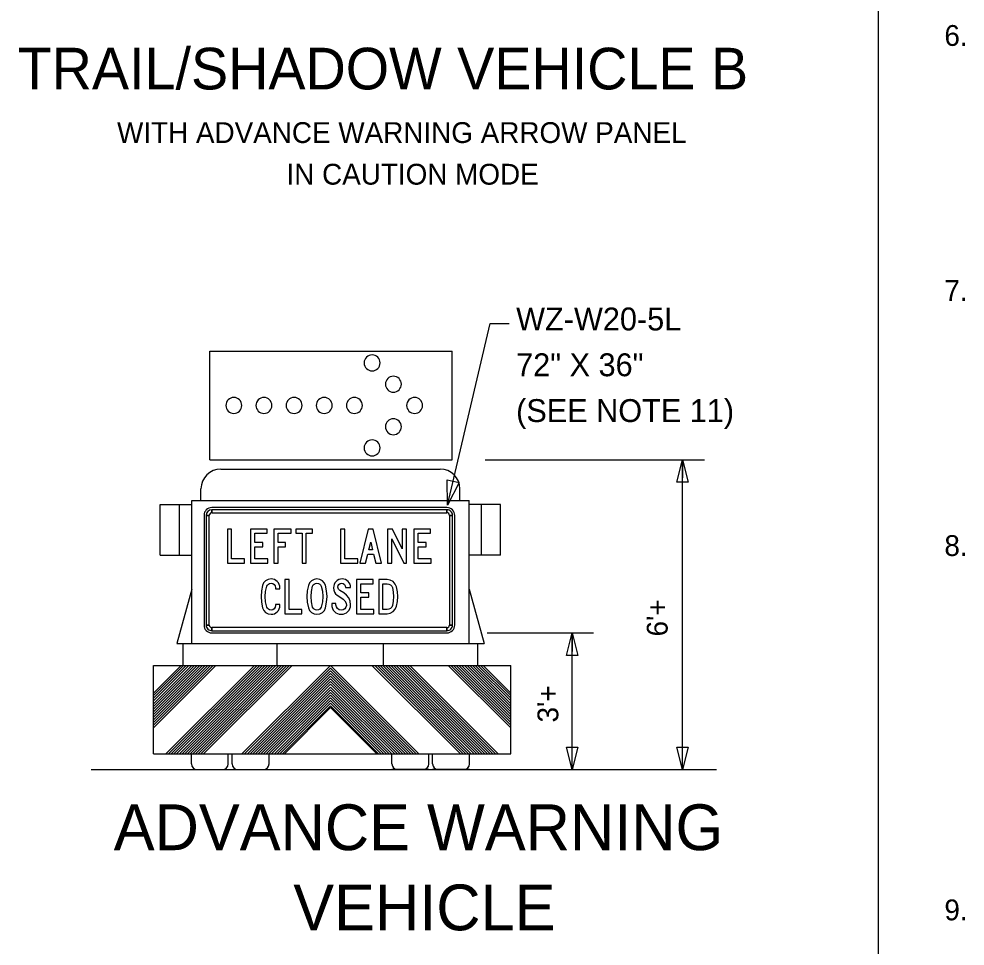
# Model space of a CAD drawing. Extents: x 1373848 to 1374003, y 380642 to 381248.
# Drawn here: x 1373929.73 to 1373956.99, y 381003.36 to 381030.08 of the extents above; entities that cross this region are included whole.
import ezdxf

# ---------------------------------------------------------------- set-up
doc = ezdxf.new("R2010")
doc.units = 0
doc.layers.add('Working Level 1', color=7, linetype='Continuous')

msp = doc.modelspace()

# ---------------------------------------------------------------- linework, layer by layer
at = {"layer": 'Working Level 1'}
for p, q in [((1373954.481, 381081.277), (1373954.481, 380977.045)), ((1373935.233, 381020.5), (1373942.211, 381020.5)), ((1373935.233, 381017.372), (1373935.233, 381020.5)), ((1373942.211, 381017.372), (1373942.211, 381020.5)), ((1373935.233, 381017.372), (1373942.211, 381017.372)), ((1373943.157, 381017.372), (1373949.484, 381017.372)), ((1373948.848, 381008.44), (1373948.848, 381017.372)), ((1373948.848, 381017.372), (1373948.848, 381016.848)), ((1373935.548, 381017.104), (1373941.862, 381017.104)), ((1373934.974, 381016.201), (1373934.974, 381016.53)), ((1373942.436, 381016.201), (1373942.436, 381016.53)), ((1373934.714, 381012.074), (1373934.714, 381016.201)), ((1373934.714, 381016.201), (1373942.696, 381016.201)), ((1373942.696, 381012.074), (1373942.696, 381016.201)), ((1373933.803, 381016.084), (1373934.714, 381016.084)), ((1373933.803, 381014.617), (1373933.803, 381016.084)), ((1373934.354, 381014.617), (1373934.354, 381016.084)), ((1373942.059, 381015.994), (1373935.288, 381015.994)), ((1373935.288, 381015.843), (1373935.288, 381015.931)), ((1373942.059, 381015.931), (1373942.059, 381015.843)), ((1373943.607, 381016.084), (1373942.696, 381016.084)), ((1373943.055, 381014.617), (1373943.055, 381016.084)), ((1373943.607, 381014.617), (1373943.607, 381016.084)), ((1373935.062, 381015.768), (1373935.062, 381012.608)), ((1373935.125, 381015.768), (1373935.213, 381015.768)), ((1373942.135, 381015.768), (1373942.222, 381015.768)), ((1373942.285, 381012.608), (1373942.285, 381015.768)), ((1373933.803, 381014.617), (1373934.714, 381014.617)), ((1373943.607, 381014.617), (1373942.696, 381014.617)), ((1373934.714, 381013.646), (1373934.282, 381012.074)), ((1373942.696, 381013.646), (1373943.128, 381012.074)), ((1373935.213, 381012.608), (1373935.125, 381012.608)), ((1373935.288, 381012.445), (1373935.288, 381012.533)), ((1373935.288, 381012.382), (1373942.059, 381012.382)), ((1373942.059, 381012.533), (1373942.059, 381012.445)), ((1373942.222, 381012.608), (1373942.135, 381012.608)), ((1373943.223, 381012.382), (1373946.284, 381012.382)), ((1373945.667, 381008.44), (1373945.667, 381012.382)), ((1373945.667, 381012.382), (1373945.667, 381011.85)), ((1373934.282, 381012.074), (1373943.128, 381012.074)), ((1373934.461, 381011.444), (1373934.461, 381012.074)), ((1373942.949, 381011.444), (1373942.949, 381012.074)), ((1373937.173, 381011.444), (1373937.173, 381012.063)), ((1373940.237, 381011.444), (1373940.237, 381012.063)), ((1373933.604, 381011.444), (1373943.899, 381011.444)), ((1373933.604, 381011.444), (1373943.899, 381011.444)), ((1373933.604, 381011.444), (1373943.899, 381011.444)), ((1373933.604, 381011.444), (1373943.899, 381011.444)), ((1373933.604, 381008.894), (1373933.604, 381011.444)), ((1373933.604, 381010.646), (1373934.402, 381011.444)), ((1373933.604, 381009.718), (1373935.33, 381011.444)), ((1373933.604, 381009.796), (1373935.252, 381011.444)), ((1373933.604, 381009.874), (1373935.174, 381011.444)), ((1373933.604, 381009.951), (1373935.097, 381011.444)), ((1373933.604, 381010.029), (1373935.019, 381011.444)), ((1373933.604, 381010.107), (1373934.941, 381011.444)), ((1373933.604, 381010.184), (1373934.864, 381011.444)), ((1373933.604, 381010.263), (1373934.786, 381011.444)), ((1373933.604, 381010.341), (1373934.707, 381011.444)), ((1373933.604, 381010.419), (1373934.629, 381011.444)), ((1373933.604, 381010.496), (1373934.552, 381011.444)), ((1373933.604, 381010.574), (1373934.474, 381011.444)), ((1373933.604, 381009.641), (1373935.405, 381011.442)), ((1373933.963, 381008.894), (1373936.513, 381011.444)), ((1373934.041, 381008.894), (1373936.591, 381011.444)), ((1373934.119, 381008.894), (1373936.669, 381011.444)), ((1373934.197, 381008.894), (1373936.747, 381011.444)), ((1373934.274, 381008.894), (1373936.824, 381011.444)), ((1373934.352, 381008.894), (1373936.902, 381011.444)), ((1373934.43, 381008.894), (1373936.98, 381011.444)), ((1373934.508, 381008.894), (1373937.058, 381011.444)), ((1373934.585, 381008.894), (1373937.135, 381011.444)), ((1373934.663, 381008.894), (1373937.213, 381011.444)), ((1373934.742, 381008.894), (1373937.291, 381011.444)), ((1373934.819, 381008.894), (1373937.368, 381011.444)), ((1373934.897, 381008.894), (1373937.446, 381011.444)), ((1373934.975, 381008.894), (1373937.523, 381011.443)), ((1373935.052, 381008.894), (1373937.602, 381011.444)), ((1373936.155, 381008.894), (1373938.705, 381011.444)), ((1373936.233, 381008.894), (1373938.705, 381011.366)), ((1373936.311, 381008.894), (1373938.705, 381011.288)), ((1373941.255, 381008.894), (1373938.705, 381011.444)), ((1373941.173, 381008.899), (1373938.705, 381011.366)), ((1373941.1, 381008.894), (1373938.705, 381011.288)), ((1373942.451, 381008.894), (1373939.901, 381011.444)), ((1373942.528, 381008.894), (1373939.98, 381011.443)), ((1373942.607, 381008.894), (1373940.057, 381011.444)), ((1373942.685, 381008.894), (1373940.135, 381011.444)), ((1373942.762, 381008.894), (1373940.212, 381011.444)), ((1373942.84, 381008.894), (1373940.29, 381011.444)), ((1373942.918, 381008.894), (1373940.368, 381011.444)), ((1373942.995, 381008.894), (1373940.445, 381011.444)), ((1373943.073, 381008.894), (1373940.523, 381011.444)), ((1373943.151, 381008.894), (1373940.601, 381011.444)), ((1373943.229, 381008.894), (1373940.679, 381011.444)), ((1373943.306, 381008.894), (1373940.756, 381011.444)), ((1373943.384, 381008.894), (1373940.834, 381011.444)), ((1373943.462, 381008.894), (1373940.913, 381011.444)), ((1373943.54, 381008.894), (1373940.99, 381011.444)), ((1373943.899, 381009.641), (1373942.098, 381011.442)), ((1373943.899, 381009.718), (1373942.173, 381011.444)), ((1373943.899, 381009.796), (1373942.251, 381011.444)), ((1373943.899, 381009.874), (1373942.329, 381011.444)), ((1373943.899, 381009.951), (1373942.406, 381011.444)), ((1373943.899, 381010.029), (1373942.484, 381011.444)), ((1373943.899, 381010.107), (1373942.563, 381011.444)), ((1373943.899, 381010.184), (1373942.64, 381011.444)), ((1373943.899, 381010.263), (1373942.718, 381011.444)), ((1373943.899, 381010.341), (1373942.796, 381011.444)), ((1373943.899, 381010.419), (1373942.874, 381011.444)), ((1373943.899, 381010.496), (1373942.951, 381011.444)), ((1373943.899, 381010.574), (1373943.029, 381011.444)), ((1373943.899, 381010.646), (1373943.101, 381011.444)), ((1373943.899, 381008.894), (1373943.899, 381011.444)), ((1373936.389, 381008.894), (1373938.705, 381011.21)), ((1373936.466, 381008.894), (1373938.705, 381011.133)), ((1373936.544, 381008.894), (1373938.705, 381011.055)), ((1373941.021, 381008.894), (1373938.705, 381011.21)), ((1373940.944, 381008.894), (1373938.705, 381011.133)), ((1373940.866, 381008.894), (1373938.705, 381011.055)), ((1373936.622, 381008.894), (1373938.705, 381010.977)), ((1373936.699, 381008.894), (1373938.705, 381010.9)), ((1373936.777, 381008.894), (1373938.705, 381010.822)), ((1373936.855, 381008.894), (1373938.705, 381010.744)), ((1373940.788, 381008.894), (1373938.705, 381010.977)), ((1373940.711, 381008.894), (1373938.705, 381010.9)), ((1373940.633, 381008.894), (1373938.705, 381010.822)), ((1373940.555, 381008.894), (1373938.705, 381010.744)), ((1373936.933, 381008.894), (1373938.705, 381010.666)), ((1373937.01, 381008.894), (1373938.705, 381010.589)), ((1373937.088, 381008.894), (1373938.705, 381010.511)), ((1373940.477, 381008.894), (1373938.705, 381010.666)), ((1373940.4, 381008.894), (1373938.705, 381010.589)), ((1373940.322, 381008.894), (1373938.705, 381010.511)), ((1373937.167, 381008.894), (1373938.705, 381010.433)), ((1373937.244, 381008.894), (1373938.705, 381010.356)), ((1373937.321, 381008.894), (1373938.705, 381010.278)), ((1373937.387, 381008.909), (1373938.705, 381010.227)), ((1373940.244, 381008.894), (1373938.705, 381010.433)), ((1373940.167, 381008.894), (1373938.705, 381010.356)), ((1373940.089, 381008.894), (1373938.705, 381010.278)), ((1373940.038, 381008.894), (1373938.705, 381010.227)), ((1373933.604, 381008.894), (1373943.899, 381008.894)), ((1373933.604, 381008.894), (1373943.899, 381008.894)), ((1373933.604, 381008.894), (1373943.899, 381008.894)), ((1373933.604, 381008.894), (1373943.899, 381008.894)), ((1373934.698, 381008.605), (1373934.698, 381008.894)), ((1373935.762, 381008.605), (1373935.762, 381008.894)), ((1373935.872, 381008.605), (1373935.872, 381008.894)), ((1373936.936, 381008.605), (1373936.936, 381008.894)), ((1373940.474, 381008.605), (1373940.474, 381008.894)), ((1373941.538, 381008.605), (1373941.538, 381008.894)), ((1373941.648, 381008.605), (1373941.648, 381008.894)), ((1373942.712, 381008.605), (1373942.712, 381008.894)), ((1373931.816, 381008.44), (1373949.828, 381008.44)), ((1373934.698, 381008.44), (1373935.762, 381008.44)), ((1373934.698, 381008.44), (1373935.762, 381008.44)), ((1373934.698, 381008.44), (1373935.762, 381008.44)), ((1373934.698, 381008.44), (1373935.762, 381008.44)), ((1373935.872, 381008.44), (1373936.936, 381008.44)), ((1373935.872, 381008.44), (1373936.936, 381008.44)), ((1373935.872, 381008.44), (1373936.936, 381008.44)), ((1373935.872, 381008.44), (1373936.936, 381008.44)), ((1373941.538, 381008.44), (1373940.474, 381008.44)), ((1373941.538, 381008.44), (1373940.474, 381008.44)), ((1373941.538, 381008.44), (1373940.474, 381008.44)), ((1373941.538, 381008.44), (1373940.474, 381008.44)), ((1373942.712, 381008.44), (1373941.648, 381008.44)), ((1373942.712, 381008.44), (1373941.648, 381008.44)), ((1373942.712, 381008.44), (1373941.648, 381008.44)), ((1373942.712, 381008.44), (1373941.648, 381008.44))]:
    msp.add_line(p, q, dxfattribs=at)
for points in [[(1373942.074, 381016.059), (1373943.308, 381021.299), (1373943.848, 381021.299)], [(1373940.175, 381014.389), (1373939.935, 381015.374), (1373939.795, 381015.374), (1373939.555, 381014.389), (1373939.718, 381014.389), (1373939.782, 381014.653), (1373939.947, 381014.653), (1373940.012, 381014.389), (1373940.175, 381014.389)], [(1373939.918, 381014.776), (1373939.812, 381014.776), (1373939.865, 381014.993), (1373939.918, 381014.776)], [(1373938.606, 381013.427), (1373938.594, 381013.593), (1373938.561, 381013.753), (1373938.527, 381013.827), (1373938.471, 381013.886), (1373938.398, 381013.924), (1373938.315, 381013.937), (1373938.232, 381013.924), (1373938.159, 381013.885), (1373938.102, 381013.826), (1373938.068, 381013.752), (1373938.036, 381013.592), (1373938.025, 381013.427), (1373938.036, 381013.264), (1373938.068, 381013.104), (1373938.102, 381013.029), (1373938.159, 381012.969), (1373938.232, 381012.93), (1373938.315, 381012.917), (1373938.398, 381012.93), (1373938.472, 381012.969), (1373938.529, 381013.03), (1373938.562, 381013.105), (1373938.595, 381013.265), (1373938.606, 381013.427)], [(1373938.482, 381013.427), (1373938.472, 381013.275), (1373938.439, 381013.126), (1373938.422, 381013.091), (1373938.394, 381013.064), (1373938.357, 381013.046), (1373938.315, 381013.04), (1373938.273, 381013.046), (1373938.237, 381013.064), (1373938.208, 381013.093), (1373938.191, 381013.127), (1373938.159, 381013.276), (1373938.148, 381013.427), (1373938.159, 381013.579), (1373938.191, 381013.727), (1373938.208, 381013.762), (1373938.237, 381013.79), (1373938.273, 381013.808), (1373938.315, 381013.814), (1373938.357, 381013.808), (1373938.394, 381013.79), (1373938.422, 381013.762), (1373938.439, 381013.728), (1373938.472, 381013.58), (1373938.482, 381013.427)], [(1373940.095, 381012.934), (1373940.335, 381012.934), (1373940.428, 381012.949), (1373940.51, 381012.995), (1373940.573, 381013.063), (1373940.609, 381013.148), (1373940.633, 381013.285), (1373940.641, 381013.427), (1373940.633, 381013.568), (1373940.609, 381013.706), (1373940.573, 381013.79), (1373940.51, 381013.859), (1373940.428, 381013.904), (1373940.335, 381013.92), (1373940.095, 381013.92), (1373940.095, 381012.934)], [(1373940.218, 381013.057), (1373940.218, 381013.796), (1373940.339, 381013.796), (1373940.389, 381013.789), (1373940.433, 381013.765), (1373940.468, 381013.729), (1373940.487, 381013.685), (1373940.51, 381013.557), (1373940.517, 381013.427), (1373940.51, 381013.296), (1373940.487, 381013.168), (1373940.468, 381013.124), (1373940.433, 381013.089), (1373940.389, 381013.065), (1373940.339, 381013.057), (1373940.218, 381013.057)]]:
    msp.add_lwpolyline(points, dxfattribs=at)
for points in [[(1373948.685, 381016.722), (1373948.848, 381017.372), (1373949.01, 381016.722)], [(1373942.412, 381016.714), (1373942.074, 381016.059), (1373942.064, 381016.796)], [(1373942.059, 381015.931), (1373935.288, 381015.931), (1373935.288, 381015.843), (1373942.059, 381015.843), (1373942.059, 381015.931)], [(1373935.125, 381015.768), (1373935.125, 381012.608), (1373935.213, 381012.608), (1373935.213, 381015.768), (1373935.125, 381015.768)], [(1373942.222, 381012.608), (1373942.222, 381015.768), (1373942.135, 381015.768), (1373942.135, 381012.608), (1373942.222, 381012.608)], [(1373936.231, 381014.389), (1373936.231, 381014.512), (1373935.858, 381014.512), (1373935.858, 381015.374), (1373935.735, 381015.374), (1373935.735, 381014.389)], [(1373936.902, 381014.389), (1373936.902, 381014.512), (1373936.529, 381014.512), (1373936.529, 381014.864), (1373936.758, 381014.864), (1373936.758, 381014.987), (1373936.529, 381014.987), (1373936.529, 381015.251), (1373936.886, 381015.251), (1373936.886, 381015.374), (1373936.406, 381015.374), (1373936.406, 381014.389)], [(1373937.573, 381015.251), (1373937.573, 381015.374), (1373937.077, 381015.374), (1373937.077, 381014.389), (1373937.2, 381014.389), (1373937.2, 381014.864), (1373937.411, 381014.864), (1373937.411, 381014.987), (1373937.2, 381014.987), (1373937.2, 381015.251)], [(1373938.185, 381015.251), (1373938.185, 381015.374), (1373937.71, 381015.374), (1373937.71, 381015.251), (1373937.886, 381015.251), (1373937.886, 381014.389), (1373938.009, 381014.389), (1373938.009, 381015.251)], [(1373939.493, 381014.389), (1373939.493, 381014.512), (1373939.119, 381014.512), (1373939.119, 381015.374), (1373938.996, 381015.374), (1373938.996, 381014.389)], [(1373940.897, 381014.389), (1373940.897, 381015.374), (1373940.773, 381015.374), (1373940.773, 381014.8), (1373940.494, 381015.374), (1373940.351, 381015.374), (1373940.351, 381014.389), (1373940.474, 381014.389), (1373940.474, 381015.093), (1373940.817, 381014.389)], [(1373941.607, 381014.389), (1373941.607, 381014.512), (1373941.234, 381014.512), (1373941.234, 381014.864), (1373941.463, 381014.864), (1373941.463, 381014.987), (1373941.234, 381014.987), (1373941.234, 381015.251), (1373941.591, 381015.251), (1373941.591, 381015.374), (1373941.111, 381015.374), (1373941.111, 381014.389)], [(1373937.249, 381013.198), (1373937.126, 381013.198), (1373937.126, 381013.17), (1373937.116, 381013.12), (1373937.087, 381013.078), (1373937.045, 381013.049), (1373936.995, 381013.04), (1373936.953, 381013.046), (1373936.916, 381013.064), (1373936.887, 381013.093), (1373936.87, 381013.127), (1373936.837, 381013.275), (1373936.827, 381013.427), (1373936.837, 381013.578), (1373936.87, 381013.725), (1373936.887, 381013.761), (1373936.916, 381013.789), (1373936.953, 381013.808), (1373936.995, 381013.814), (1373937.045, 381013.804), (1373937.087, 381013.776), (1373937.116, 381013.733), (1373937.126, 381013.684), (1373937.126, 381013.656), (1373937.249, 381013.656), (1373937.249, 381013.681), (1373937.245, 381013.732), (1373937.23, 381013.779), (1373937.207, 381013.822), (1373937.174, 381013.862), (1373937.135, 381013.895), (1373937.092, 381013.918), (1373937.044, 381013.932), (1373936.993, 381013.937), (1373936.91, 381013.924), (1373936.837, 381013.884), (1373936.78, 381013.824), (1373936.745, 381013.749), (1373936.714, 381013.589), (1373936.704, 381013.427), (1373936.714, 381013.263), (1373936.746, 381013.104), (1373936.781, 381013.029), (1373936.837, 381012.969), (1373936.91, 381012.93), (1373936.993, 381012.917), (1373937.044, 381012.921), (1373937.092, 381012.935), (1373937.135, 381012.959), (1373937.174, 381012.992), (1373937.207, 381013.031), (1373937.23, 381013.075), (1373937.245, 381013.122), (1373937.249, 381013.173)], [(1373937.884, 381012.934), (1373937.884, 381013.057), (1373937.511, 381013.057), (1373937.511, 381013.92), (1373937.388, 381013.92), (1373937.388, 381012.934)], [(1373938.74, 381013.233), (1373938.74, 381013.193), (1373938.745, 381013.138), (1373938.76, 381013.087), (1373938.785, 381013.04), (1373938.82, 381012.997), (1373938.862, 381012.962), (1373938.908, 381012.937), (1373938.958, 381012.922), (1373939.013, 381012.917), (1373939.067, 381012.922), (1373939.118, 381012.936), (1373939.164, 381012.961), (1373939.206, 381012.997), (1373939.241, 381013.039), (1373939.266, 381013.085), (1373939.281, 381013.135), (1373939.286, 381013.189), (1373939.272, 381013.294), (1373939.231, 381013.391), (1373939.168, 381013.473), (1373939.086, 381013.537), (1373938.979, 381013.604), (1373938.932, 381013.645), (1373938.916, 381013.701), (1373938.925, 381013.744), (1373938.949, 381013.781), (1373938.986, 381013.806), (1373939.028, 381013.814), (1373939.071, 381013.805), (1373939.108, 381013.778), (1373939.132, 381013.738), (1373939.141, 381013.691), (1373939.286, 381013.691), (1373939.281, 381013.74), (1373939.268, 381013.785), (1373939.245, 381013.827), (1373939.213, 381013.865), (1373939.175, 381013.896), (1373939.134, 381013.919), (1373939.088, 381013.933), (1373939.039, 381013.937), (1373938.99, 381013.933), (1373938.944, 381013.919), (1373938.902, 381013.895), (1373938.865, 381013.863), (1373938.833, 381013.824), (1373938.811, 381013.781), (1373938.798, 381013.734), (1373938.793, 381013.684), (1373938.799, 381013.616), (1373938.819, 381013.557), (1373938.852, 381013.507), (1373938.898, 381013.465), (1373939.005, 381013.4), (1373939.074, 381013.357), (1373939.123, 381013.304), (1373939.153, 381013.243), (1373939.163, 381013.172), (1373939.152, 381013.121), (1373939.119, 381013.078), (1373939.07, 381013.049), (1373939.013, 381013.04), (1373938.955, 381013.05), (1373938.907, 381013.083), (1373938.874, 381013.132), (1373938.864, 381013.189), (1373938.864, 381013.233)], [(1373939.954, 381012.934), (1373939.954, 381013.057), (1373939.581, 381013.057), (1373939.581, 381013.409), (1373939.81, 381013.409), (1373939.81, 381013.532), (1373939.581, 381013.532), (1373939.581, 381013.796), (1373939.939, 381013.796), (1373939.939, 381013.92), (1373939.458, 381013.92), (1373939.458, 381012.934)], [(1373935.288, 381012.445), (1373942.059, 381012.445), (1373942.059, 381012.533), (1373935.288, 381012.533), (1373935.288, 381012.445)], [(1373945.504, 381011.732), (1373945.667, 381012.382), (1373945.829, 381011.732)], [(1373945.829, 381009.09), (1373945.667, 381008.44), (1373945.504, 381009.09)], [(1373949.01, 381009.09), (1373948.848, 381008.44), (1373948.685, 381009.09)]]:
    msp.add_lwpolyline(points, close=True, dxfattribs=at)
for centre, radius, start, end in [((1373939.905, 381020.162), 0.23, 0, 180), ((1373939.905, 381020.162), 0.23, 180, 0), ((1373940.517, 381019.549), 0.23, 0, 180), ((1373940.517, 381019.549), 0.23, 180, 0), ((1373935.921, 381018.936), 0.23, 0, 180), ((1373936.789, 381018.936), 0.23, 0, 180), ((1373937.657, 381018.936), 0.23, 0, 180), ((1373938.525, 381018.936), 0.23, 0, 180), ((1373939.393, 381018.936), 0.23, 0, 180), ((1373941.129, 381018.936), 0.23, 0, 180), ((1373935.921, 381018.936), 0.23, 180, 0), ((1373936.789, 381018.936), 0.23, 180, 0), ((1373937.657, 381018.936), 0.23, 180, 0), ((1373938.525, 381018.936), 0.23, 180, 0), ((1373939.393, 381018.936), 0.23, 180, 0), ((1373941.129, 381018.936), 0.23, 180, 0), ((1373940.517, 381018.324), 0.23, 0, 180), ((1373940.517, 381018.324), 0.23, 180, 0), ((1373939.905, 381017.712), 0.23, 0, 180), ((1373939.905, 381017.712), 0.23, 180, 0), ((1373935.548, 381016.53), 0.574, 90, 180), ((1373941.862, 381016.53), 0.574, 0, 90), ((1373935.288, 381015.768), 0.226, 90.0002, 179.9998), ((1373935.288, 381015.768), 0.163, 90.0002, 179.9998), ((1373942.059, 381015.768), 0.226, 0, 90.0002), ((1373942.059, 381015.768), 0.163, 0, 90.0002), ((1373935.288, 381015.768), 0.0752, 90.0002, 179.9998), ((1373942.059, 381015.768), 0.0752, 0, 90.0002), ((1373935.288, 381012.608), 0.226, 179.9998, 270.0001), ((1373935.288, 381012.608), 0.163, 179.9998, 270.0001), ((1373935.288, 381012.608), 0.0752, 179.9998, 270.0001), ((1373942.059, 381012.608), 0.226, 270.0001, 0.0003), ((1373942.059, 381012.608), 0.163, 270.0001, 0.0003), ((1373942.059, 381012.608), 0.0752, 270.0001, 0.0003), ((1373934.863, 381008.605), 0.165, 180, 270), ((1373935.597, 381008.605), 0.165, 270, 0), ((1373936.037, 381008.605), 0.165, 180, 270), ((1373936.771, 381008.605), 0.165, 270, 0), ((1373940.639, 381008.605), 0.165, 180, 270), ((1373941.373, 381008.605), 0.165, 270, 0), ((1373941.813, 381008.605), 0.165, 180, 270), ((1373942.547, 381008.605), 0.165, 270, 0)]:
    msp.add_arc(centre, radius, start, end, dxfattribs=at)

# ---------------------------------------------------------------- texts
for s, height, p in [('6. ', 0.6, (1373956.39, 381029.298)), ('TRAIL/SHADOW VEHICLE B', 1.2, (1373929.694, 381028.044)), ('WITH ADVANCE WARNING ARROW PANEL', 0.6, (1373932.557, 381026.5)), ('IN CAUTION MODE', 0.6, (1373937.438, 381025.3)), ('7. ', 0.6, (1373956.39, 381021.948)), ('WZ-W20-5L', 0.66, (1373944.053, 381021.098)), ('72" X 36"', 0.66, (1373944.053, 381019.778)), ('(SEE NOTE 11)', 0.66, (1373944.053, 381018.458)), ('8.', 0.6, (1373956.39, 381014.598)), ('ADVANCE WARNING', 1.32, (1373932.462, 381006.12)), ('VEHICLE ', 1.32, (1373937.633, 381003.81)), ('9.', 0.6, (1373956.39, 381004.098))]:
    msp.add_text(s, height=height, dxfattribs=at).set_placement(p)
for s, p in [("6'+", (1373948.418, 381012.28)), ("3'+", (1373945.268, 381009.8))]:
    msp.add_text(s, height=0.6, rotation=90, dxfattribs=at).set_placement(p)

doc.saveas('drawing.dxf')
